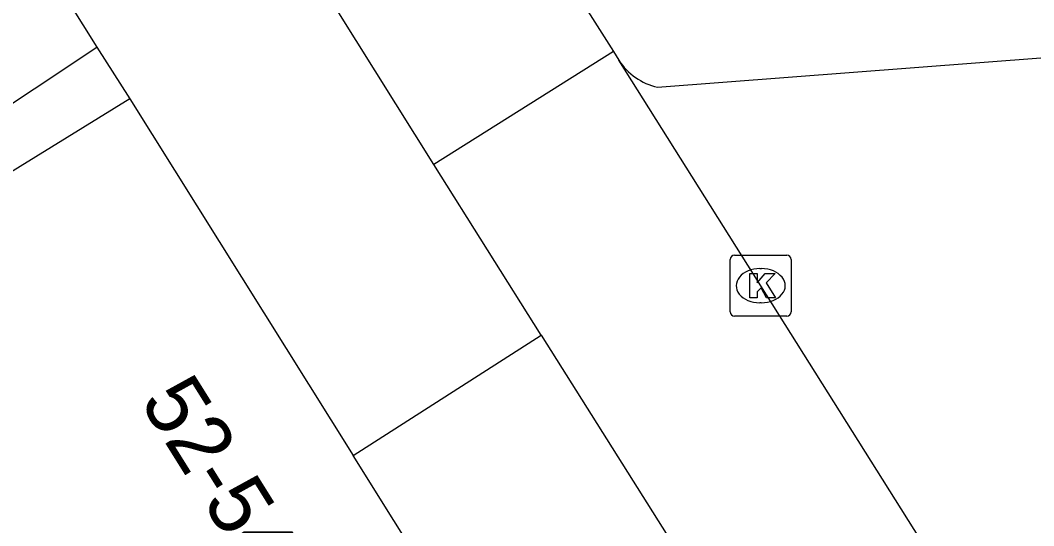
# Model space of a CAD drawing. Extents: x 161801 to 162379, y 382315 to 382832.
# Drawn here: x 162071.44 to 162088.01, y 382518.38 to 382526.64 of the extents above; entities that cross this region are included whole.
import ezdxf

# ---------------------------------------------------------------- set-up
doc = ezdxf.new("R2010")
doc.units = 0
for name, color, linetype in [('IMGEO_Kolk', 7, 'Continuous'), ('IMGEO_Pand', 7, 'Continuous'), ('IMGEO_Pand_nummerreeks', 7, 'Continuous'), ('IMGEO_Rijbaan_lokaal_open', 7, 'Continuous'), ('IMGEO_Voetpad_open', 7, 'Continuous')]:
    doc.layers.add(name, color=color, linetype=linetype)

msp = doc.modelspace()

# ---------------------------------------------------------------- linework, layer by layer
at = {"layer": 'IMGEO_Kolk'}
for p, q in [((162083.121, 382522.801), (162083.973, 382522.801)), ((162083.046, 382521.875), (162083.046, 382522.727)), ((162084.047, 382522.727), (162084.047, 382521.875)), ((162083.534, 382522.581), (162083.559, 382522.581)), ((162083.557, 382522.021), (162083.532, 382522.021)), ((162083.973, 382521.801), (162083.121, 382521.801))]:
    msp.add_line(p, q, dxfattribs=at)
for points in [[(162083.121, 382522.801), (162083.973, 382522.801)], [(162083.046, 382521.875), (162083.046, 382522.727)], [(162084.047, 382522.727), (162084.047, 382521.875)], [(162083.367, 382522.501), (162083.49, 382522.501), (162083.49, 382522.35), (162083.62, 382522.501), (162083.784, 382522.501), (162083.638, 382522.35), (162083.791, 382522.101), (162083.639, 382522.101), (162083.554, 382522.265), (162083.49, 382522.198), (162083.49, 382522.101), (162083.367, 382522.101), (162083.367, 382522.501)], [(162083.973, 382521.801), (162083.121, 382521.801)]]:
    msp.add_lwpolyline(points, dxfattribs=at)
for centre, start, end in [((162083.123, 382522.725), 91.552, 178.448), ((162083.123, 382522.725), 91.552, 178.448), ((162083.971, 382522.725), 1.552, 88.448), ((162083.971, 382522.725), 1.552, 88.448), ((162083.123, 382521.877), 181.552, 268.448), ((162083.123, 382521.877), 181.552, 268.448), ((162083.971, 382521.877), 271.552, 358.448), ((162083.971, 382521.877), 271.552, 358.448)]:
    msp.add_arc(centre, 0.0765, start, end, dxfattribs=at)
for centre, major_axis, ratio, start_param, end_param in [((162083.533, 382522.301), (-0.387, 0.002), 0.722429, 4.712389, 7.853982), ((162083.558, 382522.301), (-0.39, 0.002), 0.717154, 1.570796, 4.712389)]:
    msp.add_ellipse(centre, major_axis=major_axis, ratio=ratio, start_param=start_param, end_param=end_param, dxfattribs=at)
at = {"layer": 'IMGEO_Pand'}
for points in [[(162069.305, 382531.6), (162072.69, 382526.201)], [(162054.668, 382522.408), (162056.716, 382519.203), (162056.811, 382519.053), (162064.227, 382523.721), (162065.573, 382521.582), (162068.589, 382523.477), (162072.69, 382526.201)], [(162073.232, 382525.358), (162069.058, 382522.785), (162065.94, 382520.822)], [(162073.232, 382525.358), (162076.885, 382519.522)], [(162078.879, 382516.336), (162076.885, 382519.522)]]:
    msp.add_lwpolyline(points, dxfattribs=at)
at = {"layer": 'IMGEO_Rijbaan_lokaal_open'}
for points in [[(162080.1, 382527.774), (162081.138, 382526.129)], [(162078.203, 382524.285), (162076.622, 382526.804)], [(162081.138, 382526.129), (162078.203, 382524.285)], [(162081.138, 382526.129), (162081.227, 382525.987)], [(162091.281, 382510.003), (162081.227, 382525.987)], [(162079.956, 382521.492), (162078.203, 382524.285)], [(162079.956, 382521.492), (162082.029, 382518.203)]]:
    msp.add_lwpolyline(points, dxfattribs=at)
at = {"layer": 'IMGEO_Voetpad_open'}
for points in [[(162072.69, 382526.201), (162073.232, 382525.358)], [(162081.859, 382525.548), (162088.201, 382526.034)], [(162076.885, 382519.522), (162079.956, 382521.492)]]:
    msp.add_lwpolyline(points, dxfattribs=at)
msp.add_arc((162082.084, 382526.547), 1.024, 213.1429, 257.2878, dxfattribs=at)

# ---------------------------------------------------------------- texts
at = {"layer": 'IMGEO_Pand_nummerreeks'}
msp.add_text('52-54', height=1, rotation=302.0453, dxfattribs=at).set_placement((162073.383, 382520.405))

doc.saveas('drawing.dxf')
